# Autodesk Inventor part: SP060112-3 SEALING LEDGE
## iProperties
Created: 2012-06
Part Number: SP060112-3 SEALING LEDGE
Material: Rubber
Document SubType Name: Modeling
Designer: Administrator
Density: 0.93 g/cm^3
Mass: 85.0608 g
Surface Area: 980.433 cm^2
Volume: 91.4633 cm^3
Author: Administrator
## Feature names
1. Extrusion1
